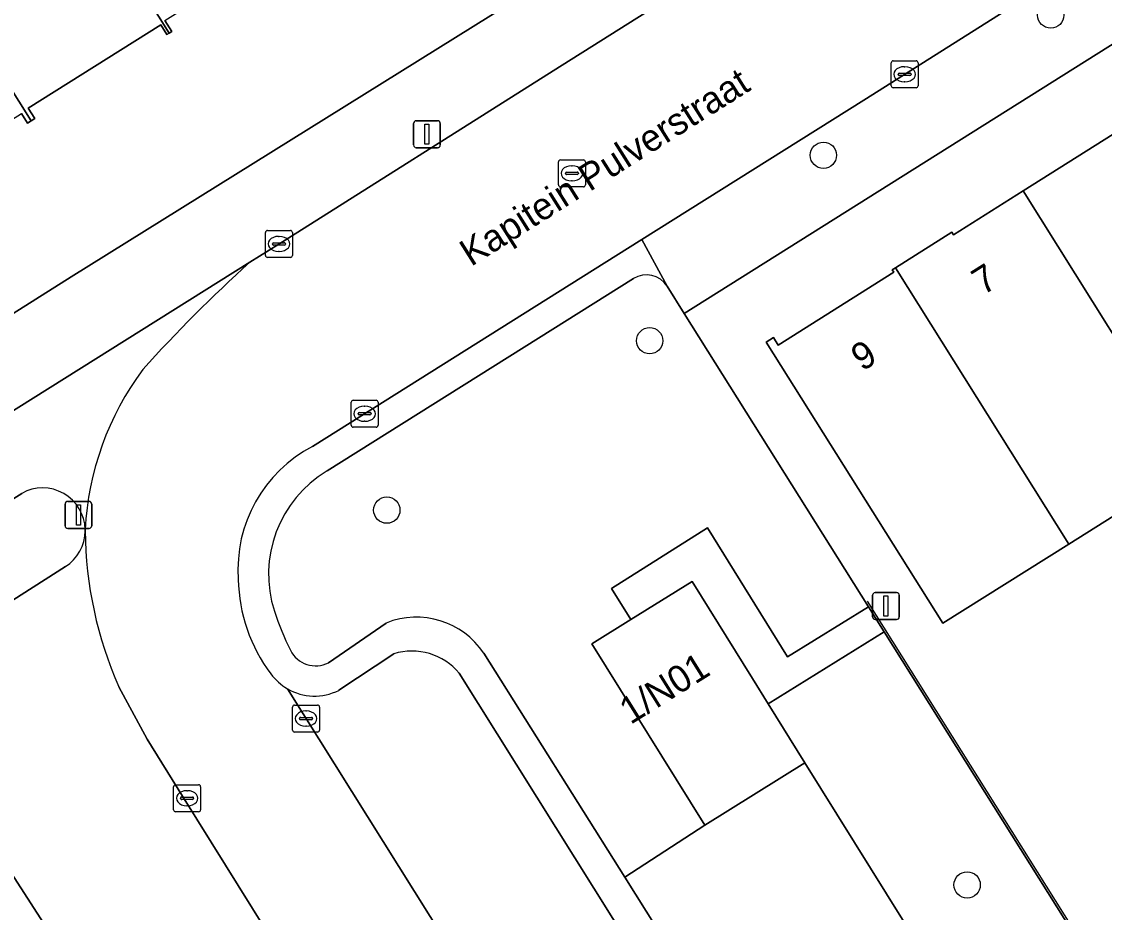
# Model space of a CAD drawing. Extents: x 160077 to 160948, y 386481 to 387498.
# Drawn here: x 160384.29 to 160424.49, y 386952.63 to 386985.67 of the extents above; entities that cross this region are included whole.
import ezdxf

# ---------------------------------------------------------------- set-up
doc = ezdxf.new("R2010")
doc.units = 0
for name, color, linetype in [('IMGEO_Boom', 7, 'Continuous'), ('IMGEO_Erf', 7, 'Continuous'), ('IMGEO_Fietspad_open', 7, 'Continuous'), ('IMGEO_Groenvoorziening', 7, 'Continuous'), ('IMGEO_Hek', 7, 'Continuous'), ('IMGEO_Kolk', 7, 'Continuous'), ('IMGEO_Lichtmast', 7, 'Continuous'), ('IMGEO_Openbare_ruimte_label', 7, 'Continuous'), ('IMGEO_Pand', 7, 'Continuous'), ('IMGEO_Pand_nummerreeks', 7, 'Continuous'), ('IMGEO_Parkeervlak_open', 7, 'Continuous'), ('IMGEO_Rijbaan_lokaal_open', 7, 'Continuous'), ('IMGEO_Rioolput', 7, 'Continuous'), ('IMGEO_Voetpad_open', 7, 'Continuous')]:
    doc.layers.add(name, color=color, linetype=linetype)

msp = doc.modelspace()

# ---------------------------------------------------------------- linework, layer by layer
at = {"layer": 'IMGEO_Boom'}
for centre in [(160422.495, 386985.915), (160414.056, 386980.712), (160407.607, 386973.835), (160397.849, 386967.551), (160419.392, 386953.648)]:
    msp.add_circle(centre, 0.489, dxfattribs=at)
at = {"layer": 'IMGEO_Erf'}
for points in [[(160473.137, 386972.655), (160453.975, 387003.205), (160430.516, 386988.451), (160431.817, 386986.382), (160437.856, 386976.782), (160436.662, 386976.031), (160430.668, 386985.657), (160429.375, 386987.733), (160408.886, 386974.847), (160415.725, 386963.966), (160416.309, 386963.036), (160430.464, 386940.512), (160434.156, 386934.637), (160441.379, 386922.838), (160445.701, 386916.313), (160449.013, 386911.065), (160450.499, 386908.528)], [(160361.943, 386960.929), (160386.133, 386976.2), (160423.489, 386999.46)], [(160389.614, 386985.706), (160389.868, 386985.302), (160389.776, 386985.245), (160389.684, 386985.187), (160389.457, 386985.548), (160384.539, 386982.455), (160384.78, 386982.073), (160384.648, 386981.99), (160384.513, 386981.905), (160384.292, 386982.257)]]:
    msp.add_lwpolyline(points, dxfattribs=at)
msp.add_lwpolyline([(160437.207, 386975.107), (160432.526, 386972.169), (160427.846, 386969.231), (160423.165, 386966.292), (160418.484, 386963.354), (160411.929, 386973.778), (160412.201, 386973.949), (160412.378, 386973.667), (160416.671, 386976.375), (160416.614, 386976.465), (160416.732, 386976.539), (160418.828, 386977.855), (160418.883, 386977.766), (160421.467, 386979.392), (160426.144, 386982.336), (160430.553, 386985.11), (160430.383, 386985.382), (160430.656, 386985.554)], close=True, dxfattribs=at)
at = {"layer": 'IMGEO_Fietspad_open'}
for points in [[(160392.767, 386976.747), (160358.891, 386955.508), (160347.47, 386948.297), (160344.021, 386946.162), (160342.931, 386945.487)], [(160371.041, 386959.892), (160375.091, 386962.445), (160384.296, 386968.171)]]:
    msp.add_lwpolyline(points, dxfattribs=at)
for centre, radius, start, end in [((160429.937, 386935.635), 55.424, 132.1175, 137.9401), ((160397.547, 386966.26), 10.91, 143.4032, 177.0031), ((160385.072, 386966.795), 1.58, 1.2748, 119.4294)]:
    msp.add_arc(centre, radius, start, end, dxfattribs=at)
at = {"layer": 'IMGEO_Groenvoorziening'}
for points in [[(160453.975, 387003.205), (160452.3, 387005.897), (160451.615, 387005.476), (160449.965, 387004.462), (160449.803, 387004.359), (160442.967, 387000.002), (160435.029, 386995.058), (160415.556, 386982.761), (160407.317, 386977.588), (160408.253, 386975.855), (160408.886, 386974.847), (160429.375, 386987.733), (160430.516, 386988.451)], [(160416.309, 386963.036), (160412.008, 386960.369), (160413.372, 386958.18), (160426.082, 386937.782), (160429.547, 386939.941), (160430.464, 386940.512)], [(160413.372, 386958.18), (160409.654, 386955.863), (160406.679, 386953.933), (160423.283, 386927.515), (160428.214, 386930.912), (160426.619, 386933.446), (160424.504, 386936.799), (160426.082, 386937.782)]]:
    msp.add_lwpolyline(points, close=True, dxfattribs=at)
for points in [[(160407.006, 386976.14), (160403.479, 386973.927), (160395.629, 386969.002)], [(160409.756, 386966.888), (160412.722, 386962.104), (160415.725, 386963.966), (160408.886, 386974.847), (160408.253, 386975.855)], [(160401.452, 386962.248), (160406.679, 386953.933), (160409.654, 386955.863), (160405.461, 386962.589), (160406.91, 386963.492), (160406.187, 386964.645), (160409.756, 386966.888)], [(160395.68, 386961.887), (160397.825, 386963.363)]]:
    msp.add_lwpolyline(points, dxfattribs=at)
for centre, radius, start, end in [((160407.486, 386975.371), 0.907, 32.2578, 121.9947), ((160397.921, 386965.172), 4.463, 120.8967, 197.9502), ((160403.403, 386966.983), 10.237, 198.1333, 206.9095), ((160398.945, 386960.549), 3.029, 34.1263, 111.6971), ((160395.209, 386962.82), 1.045, 206.7099, 296.8121)]:
    msp.add_arc(centre, radius, start, end, dxfattribs=at)
at = {"layer": 'IMGEO_Hek'}
msp.add_lwpolyline([(160447.699, 386913.245), (160415.689, 386964.174)], dxfattribs=at)
at = {"layer": 'IMGEO_Kolk'}
for p, q in [((160416.571, 386983.291), (160416.571, 386984.143)), ((160416.646, 386984.217), (160417.498, 386984.217)), ((160417.059, 386983.997), (160417.084, 386983.997)), ((160417.572, 386984.143), (160417.572, 386983.291)), ((160416.83, 386983.711), (160416.83, 386983.723)), ((160417.268, 386983.674), (160416.87, 386983.674)), ((160416.873, 386983.76), (160417.271, 386983.76)), ((160417.314, 386983.723), (160417.314, 386983.711)), ((160417.498, 386983.217), (160416.646, 386983.217)), ((160417.082, 386983.437), (160417.057, 386983.437)), ((160393.345, 386976.998), (160393.345, 386977.85)), ((160393.42, 386977.924), (160394.272, 386977.924)), ((160394.346, 386977.85), (160394.346, 386976.998)), ((160393.647, 386977.467), (160394.045, 386977.467)), ((160393.833, 386977.704), (160393.858, 386977.704)), ((160393.604, 386977.418), (160393.604, 386977.43)), ((160394.042, 386977.381), (160393.644, 386977.381)), ((160393.856, 386977.144), (160393.831, 386977.144)), ((160394.088, 386977.43), (160394.088, 386977.418)), ((160394.272, 386976.924), (160393.42, 386976.924)), ((160396.526, 386970.699), (160396.526, 386971.551)), ((160396.601, 386971.625), (160397.453, 386971.625)), ((160397.527, 386971.551), (160397.527, 386970.699)), ((160396.785, 386971.119), (160396.785, 386971.131)), ((160397.223, 386971.082), (160396.825, 386971.082)), ((160396.828, 386971.168), (160397.226, 386971.168)), ((160397.014, 386971.405), (160397.039, 386971.405)), ((160397.269, 386971.131), (160397.269, 386971.119)), ((160397.453, 386970.625), (160396.601, 386970.625)), ((160397.037, 386970.845), (160397.012, 386970.845)), ((160394.351, 386959.394), (160394.351, 386960.246)), ((160394.426, 386960.32), (160395.278, 386960.32)), ((160395.352, 386960.246), (160395.352, 386959.394)), ((160394.61, 386959.814), (160394.61, 386959.826)), ((160395.048, 386959.777), (160394.65, 386959.777)), ((160394.653, 386959.863), (160395.051, 386959.863)), ((160394.839, 386960.1), (160394.864, 386960.1)), ((160395.094, 386959.826), (160395.094, 386959.814)), ((160394.862, 386959.54), (160394.837, 386959.54)), ((160395.278, 386959.32), (160394.426, 386959.32)), ((160390.011, 386957.364), (160390.863, 386957.364)), ((160389.936, 386956.438), (160389.936, 386957.29)), ((160390.424, 386957.144), (160390.449, 386957.144)), ((160390.937, 386957.29), (160390.937, 386956.438)), ((160390.195, 386956.858), (160390.195, 386956.87)), ((160390.633, 386956.821), (160390.235, 386956.821)), ((160390.238, 386956.907), (160390.636, 386956.907)), ((160390.447, 386956.584), (160390.422, 386956.584)), ((160390.679, 386956.87), (160390.679, 386956.858)), ((160390.863, 386956.364), (160390.011, 386956.364))]:
    msp.add_line(p, q, dxfattribs=at)
for points in [[(160416.571, 386983.291), (160416.571, 386984.143)], [(160416.646, 386984.217), (160417.498, 386984.217)], [(160417.572, 386984.143), (160417.572, 386983.291)], [(160417.498, 386983.217), (160416.646, 386983.217)], [(160393.345, 386976.998), (160393.345, 386977.85)], [(160393.42, 386977.924), (160394.272, 386977.924)], [(160394.346, 386977.85), (160394.346, 386976.998)], [(160394.272, 386976.924), (160393.42, 386976.924)], [(160396.526, 386970.699), (160396.526, 386971.551)], [(160396.601, 386971.625), (160397.453, 386971.625)], [(160397.527, 386971.551), (160397.527, 386970.699)], [(160397.453, 386970.625), (160396.601, 386970.625)], [(160394.351, 386959.394), (160394.351, 386960.246)], [(160394.426, 386960.32), (160395.278, 386960.32)], [(160395.352, 386960.246), (160395.352, 386959.394)], [(160395.278, 386959.32), (160394.426, 386959.32)], [(160390.011, 386957.364), (160390.863, 386957.364)], [(160389.936, 386956.438), (160389.936, 386957.29)], [(160390.937, 386957.29), (160390.937, 386956.438)], [(160390.863, 386956.364), (160390.011, 386956.364)]]:
    msp.add_lwpolyline(points, dxfattribs=at)
for centre, radius, start, end in [((160416.648, 386984.141), 0.0765, 91.552, 178.448), ((160416.648, 386984.141), 0.0765, 91.552, 178.448), ((160417.496, 386984.141), 0.0765, 1.552, 88.448), ((160417.496, 386984.141), 0.0765, 1.552, 88.448), ((160416.87, 386983.72), 0.0403, 85.8775, 175.7526), ((160416.867, 386983.71), 0.0366, 178.938, 274.7102), ((160417.271, 386983.717), 0.043, 264.8664, 352.4533), ((160417.275, 386983.722), 0.0386, 1.7309, 96.639), ((160416.648, 386983.293), 0.0765, 181.552, 268.448), ((160416.648, 386983.293), 0.0765, 181.552, 268.448), ((160417.496, 386983.293), 0.0765, 271.552, 358.448), ((160417.496, 386983.293), 0.0765, 271.552, 358.448), ((160393.422, 386977.848), 0.0765, 91.552, 178.448), ((160393.422, 386977.848), 0.0765, 91.552, 178.448), ((160394.27, 386977.848), 0.0765, 1.552, 88.448), ((160394.27, 386977.848), 0.0765, 1.552, 88.448), ((160393.644, 386977.427), 0.0403, 85.8775, 175.7526), ((160394.049, 386977.429), 0.0386, 1.7309, 96.639), ((160393.641, 386977.417), 0.0366, 178.938, 274.7102), ((160394.045, 386977.424), 0.043, 264.8664, 352.4533), ((160393.422, 386977), 0.0765, 181.552, 268.448), ((160393.422, 386977), 0.0765, 181.552, 268.448), ((160394.27, 386977), 0.0765, 271.552, 358.448), ((160394.27, 386977), 0.0765, 271.552, 358.448), ((160396.603, 386971.549), 0.0765, 91.552, 178.448), ((160396.603, 386971.549), 0.0765, 91.552, 178.448), ((160397.451, 386971.549), 0.0765, 1.552, 88.448), ((160397.451, 386971.549), 0.0765, 1.552, 88.448), ((160396.825, 386971.128), 0.0403, 85.8775, 175.7526), ((160396.822, 386971.118), 0.0366, 178.938, 274.7102), ((160397.226, 386971.125), 0.043, 264.8664, 352.4533), ((160397.23, 386971.13), 0.0386, 1.7309, 96.639), ((160396.603, 386970.701), 0.0765, 181.552, 268.448), ((160396.603, 386970.701), 0.0765, 181.552, 268.448), ((160397.451, 386970.701), 0.0765, 271.552, 358.448), ((160397.451, 386970.701), 0.0765, 271.552, 358.448), ((160394.428, 386960.244), 0.0765, 91.552, 178.448), ((160394.428, 386960.244), 0.0765, 91.552, 178.448), ((160395.276, 386960.244), 0.0765, 1.552, 88.448), ((160395.276, 386960.244), 0.0765, 1.552, 88.448), ((160394.65, 386959.823), 0.0403, 85.8775, 175.7526), ((160394.647, 386959.813), 0.0366, 178.938, 274.7102), ((160395.051, 386959.82), 0.043, 264.8664, 352.4533), ((160395.055, 386959.825), 0.0386, 1.7309, 96.639), ((160394.428, 386959.396), 0.0765, 181.552, 268.448), ((160394.428, 386959.396), 0.0765, 181.552, 268.448), ((160395.276, 386959.396), 0.0765, 271.552, 358.448), ((160395.276, 386959.396), 0.0765, 271.552, 358.448), ((160390.013, 386957.288), 0.0765, 91.552, 178.448), ((160390.013, 386957.288), 0.0765, 91.552, 178.448), ((160390.861, 386957.288), 0.0765, 1.552, 88.448), ((160390.861, 386957.288), 0.0765, 1.552, 88.448), ((160390.235, 386956.867), 0.0403, 85.8775, 175.7526), ((160390.232, 386956.857), 0.0366, 178.938, 274.7102), ((160390.636, 386956.864), 0.043, 264.8664, 352.4533), ((160390.64, 386956.869), 0.0386, 1.7309, 96.639), ((160390.013, 386956.44), 0.0765, 181.552, 268.448), ((160390.013, 386956.44), 0.0765, 181.552, 268.448), ((160390.861, 386956.44), 0.0765, 271.552, 358.448), ((160390.861, 386956.44), 0.0765, 271.552, 358.448)]:
    msp.add_arc(centre, radius, start, end, dxfattribs=at)
for centre, major_axis, ratio, start_param, end_param in [((160417.058, 386983.717), (-0.387, 0.002), 0.722429, 4.712389, 7.853982), ((160417.083, 386983.717), (-0.39, 0.002), 0.717154, 1.570796, 4.712389), ((160393.832, 386977.424), (-0.387, 0.002), 0.722429, 4.712389, 7.853982), ((160393.857, 386977.424), (-0.39, 0.002), 0.717154, 1.570796, 4.712389), ((160397.013, 386971.125), (-0.387, 0.002), 0.722429, 4.712389, 7.853982), ((160397.038, 386971.125), (-0.39, 0.002), 0.717154, 1.570796, 4.712389), ((160394.838, 386959.82), (-0.387, 0.002), 0.722429, 4.712389, 7.853982), ((160394.863, 386959.82), (-0.39, 0.002), 0.717154, 1.570796, 4.712389), ((160390.423, 386956.864), (-0.387, 0.002), 0.722429, 4.712389, 7.853982), ((160390.448, 386956.864), (-0.39, 0.002), 0.717154, 1.570796, 4.712389)]:
    msp.add_ellipse(centre, major_axis=major_axis, ratio=ratio, start_param=start_param, end_param=end_param, dxfattribs=at)
at = {"layer": 'IMGEO_Lichtmast'}
for p, q in [((160398.843, 386981.094), (160398.843, 386981.894)), ((160398.843, 386981.894), (160398.843, 386981.094)), ((160398.943, 386981.994), (160399.733, 386981.994)), ((160399.733, 386981.994), (160398.943, 386981.994)), ((160399.833, 386981.894), (160399.833, 386981.094)), ((160399.833, 386981.094), (160399.833, 386981.894)), ((160399.733, 386980.994), (160398.943, 386980.994)), ((160398.943, 386980.994), (160399.733, 386980.994)), ((160386.005, 386967.873), (160386.795, 386967.873)), ((160386.795, 386967.873), (160386.005, 386967.873)), ((160385.905, 386966.973), (160385.905, 386967.773)), ((160385.905, 386967.773), (160385.905, 386966.973)), ((160386.895, 386967.773), (160386.895, 386966.973)), ((160386.895, 386966.973), (160386.895, 386967.773)), ((160386.795, 386966.873), (160386.005, 386966.873)), ((160386.005, 386966.873), (160386.795, 386966.873)), ((160415.882, 386963.592), (160415.882, 386964.392)), ((160415.882, 386964.392), (160415.882, 386963.592)), ((160415.982, 386964.492), (160416.772, 386964.492)), ((160416.772, 386964.492), (160415.982, 386964.492)), ((160416.872, 386964.392), (160416.872, 386963.592)), ((160416.872, 386963.592), (160416.872, 386964.392)), ((160416.772, 386963.492), (160415.982, 386963.492)), ((160415.982, 386963.492), (160416.772, 386963.492))]:
    msp.add_line(p, q, dxfattribs=at)
for points in [[(160399.263, 386981.869), (160399.413, 386981.869), (160399.413, 386981.119), (160399.263, 386981.119), (160399.263, 386981.869)], [(160386.325, 386967.748), (160386.475, 386967.748), (160386.475, 386966.998), (160386.325, 386966.998), (160386.325, 386967.748)], [(160416.302, 386964.367), (160416.452, 386964.367), (160416.452, 386963.617), (160416.302, 386963.617), (160416.302, 386964.367)]]:
    msp.add_lwpolyline(points, dxfattribs=at)
for centre, start, end in [((160398.943, 386981.894), 90, 180), ((160398.943, 386981.894), 90, 180), ((160399.733, 386981.894), 0, 90), ((160399.733, 386981.894), 360, 90), ((160398.943, 386981.094), 180, 270), ((160398.943, 386981.094), 180, 270), ((160399.733, 386981.094), 270, 0), ((160399.733, 386981.094), 270, 0), ((160386.005, 386967.773), 90, 180), ((160386.005, 386967.773), 90, 180), ((160386.795, 386967.773), 0, 90), ((160386.795, 386967.773), 360, 90), ((160386.005, 386966.973), 180, 270), ((160386.005, 386966.973), 180, 270), ((160386.795, 386966.973), 270, 0), ((160386.795, 386966.973), 270, 0), ((160415.982, 386964.392), 90, 180), ((160415.982, 386964.392), 90, 180), ((160416.772, 386964.392), 0, 90), ((160416.772, 386964.392), 360, 90), ((160415.982, 386963.592), 180, 270), ((160415.982, 386963.592), 180, 270), ((160416.772, 386963.592), 270, 0), ((160416.772, 386963.592), 270, 0)]:
    msp.add_arc(centre, 0.1, start, end, dxfattribs=at)
at = {"layer": 'IMGEO_Pand'}
for points in [[(160390.709, 386995.08), (160385.602, 386991.891), (160389.776, 386985.245), (160389.868, 386985.302), (160389.614, 386985.706), (160394.508, 386988.784), (160394.735, 386988.423), (160394.846, 386988.493)], [(160384.648, 386981.99), (160384.78, 386982.073), (160384.539, 386982.455), (160389.457, 386985.548), (160389.684, 386985.187), (160389.776, 386985.245), (160385.602, 386991.891), (160380.45, 386988.673)], [(160379.505, 386978.742), (160379.617, 386978.812), (160379.389, 386979.174), (160384.292, 386982.257), (160384.513, 386981.905), (160384.648, 386981.99), (160380.45, 386988.673), (160375.291, 386985.452)], [(160426.144, 386982.336), (160421.467, 386979.392), (160427.846, 386969.231), (160432.526, 386972.169)], [(160421.467, 386979.392), (160418.883, 386977.766), (160418.828, 386977.855), (160416.732, 386976.539), (160423.165, 386966.292), (160427.846, 386969.231)], [(160416.732, 386976.539), (160416.614, 386976.465), (160416.671, 386976.375), (160412.378, 386973.667), (160412.201, 386973.949), (160411.929, 386973.778), (160418.484, 386963.354), (160423.165, 386966.292)], [(160411.427, 386961.301), (160409.179, 386964.907), (160406.91, 386963.492), (160405.461, 386962.589), (160409.654, 386955.863), (160413.372, 386958.18), (160412.008, 386960.369)]]:
    msp.add_lwpolyline(points, close=True, dxfattribs=at)
at = {"layer": 'IMGEO_Parkeervlak_open'}
for points in [[(160385.916, 386965.458), (160379.288, 386961.228), (160386.077, 386950.727), (160387.305, 386948.746), (160389.414, 386950.096)], [(160398.108, 386962.224), (160396.066, 386960.866)], [(160394.157, 386960.926), (160407.72, 386939.3), (160421.339, 386917.461), (160423.535, 386918.746), (160426.233, 386920.508), (160400.541, 386961.501)], [(160390.779, 386948.087), (160388.615, 386946.721), (160388.875, 386946.31), (160390.688, 386943.438), (160411.153, 386911.02), (160416.321, 386914.248), (160416.924, 386914.647), (160402.32, 386937.614), (160390.263, 386956.936), (160388.955, 386959.055), (160387.906, 386960.997)]]:
    msp.add_lwpolyline(points, dxfattribs=at)
for centre, radius, start, end in [((160385.075, 386966.792), 1.577, 302.2191, 359.5319), ((160401.172, 386966.901), 14.521, 180.4821, 203.9915), ((160398.777, 386960.021), 2.302, 39.9942, 106.9057), ((160395.167, 386962.657), 2.004, 239.7466, 296.6529)]:
    msp.add_arc(centre, radius, start, end, dxfattribs=at)
at = {"layer": 'IMGEO_Rijbaan_lokaal_open'}
for points in [[(160435.029, 386995.058), (160442.967, 387000.002), (160449.803, 387004.359), (160449.965, 387004.462), (160451.615, 387005.476), (160448.207, 387011.088), (160447.956, 387011.473), (160446.914, 387010.811), (160443.332, 387008.554), (160429.747, 387000), (160420.855, 386994.441), (160404.019, 386983.85), (160393.843, 386977.421), (160392.767, 386976.747)], [(160395.093, 386969.913), (160407.317, 386977.588), (160415.556, 386982.761), (160435.029, 386995.058)], [(160386.652, 386966.83), (160386.652, 386966.779)], [(160387.906, 386960.997), (160388.955, 386959.055), (160390.263, 386956.936), (160402.32, 386937.614), (160416.924, 386914.647), (160416.321, 386914.248), (160419.644, 386908.926), (160414.476, 386905.699), (160418.626, 386899.176), (160445.701, 386916.313), (160441.379, 386922.838), (160437.094, 386920.111), (160426.867, 386913.603), (160423.535, 386918.746), (160421.339, 386917.461), (160407.72, 386939.3), (160394.157, 386960.926)]]:
    msp.add_lwpolyline(points, dxfattribs=at)
for centre, radius, start, end in [((160429.937, 386935.635), 55.424, 132.1175, 137.9401), ((160397.547, 386966.26), 10.91, 143.4032, 177.0031), ((160397.459, 386965.354), 5.136, 117.4286, 184.141), ((160401.172, 386966.901), 14.521, 180.4821, 203.9915), ((160398.309, 386965.084), 5.974, 180.9722, 217.1576), ((160395.155, 386962.643), 1.986, 215.9898, 239.8386)]:
    msp.add_arc(centre, radius, start, end, dxfattribs=at)
at = {"layer": 'IMGEO_Rioolput'}
for p, q in [((160404.219, 386979.616), (160404.219, 386980.468)), ((160404.294, 386980.542), (160405.146, 386980.542)), ((160404.707, 386980.322), (160404.732, 386980.322)), ((160405.22, 386980.468), (160405.22, 386979.616)), ((160404.478, 386980.036), (160404.478, 386980.048)), ((160404.916, 386979.999), (160404.518, 386979.999)), ((160404.521, 386980.085), (160404.919, 386980.085)), ((160404.962, 386980.048), (160404.962, 386980.036)), ((160405.146, 386979.542), (160404.294, 386979.542)), ((160404.73, 386979.762), (160404.705, 386979.762))]:
    msp.add_line(p, q, dxfattribs=at)
for points in [[(160404.219, 386979.616), (160404.219, 386980.468)], [(160404.294, 386980.542), (160405.146, 386980.542)], [(160405.22, 386980.468), (160405.22, 386979.616)], [(160405.146, 386979.542), (160404.294, 386979.542)]]:
    msp.add_lwpolyline(points, dxfattribs=at)
for centre, radius, start, end in [((160404.296, 386980.466), 0.0765, 91.552, 178.448), ((160404.296, 386980.466), 0.0765, 91.552, 178.448), ((160405.144, 386980.466), 0.0765, 1.552, 88.448), ((160405.144, 386980.466), 0.0765, 1.552, 88.448), ((160404.518, 386980.045), 0.0403, 85.8775, 175.7526), ((160404.515, 386980.035), 0.0366, 178.938, 274.7102), ((160404.919, 386980.042), 0.043, 264.8664, 352.4533), ((160404.923, 386980.047), 0.0386, 1.7309, 96.639), ((160404.296, 386979.618), 0.0765, 181.552, 268.448), ((160404.296, 386979.618), 0.0765, 181.552, 268.448), ((160405.144, 386979.618), 0.0765, 271.552, 358.448), ((160405.144, 386979.618), 0.0765, 271.552, 358.448)]:
    msp.add_arc(centre, radius, start, end, dxfattribs=at)
for centre, major_axis, ratio, start_param, end_param in [((160404.706, 386980.042), (-0.387, 0.002), 0.722429, 4.712389, 7.853982), ((160404.731, 386980.042), (-0.39, 0.002), 0.717154, 1.570796, 4.712389)]:
    msp.add_ellipse(centre, major_axis=major_axis, ratio=ratio, start_param=start_param, end_param=end_param, dxfattribs=at)
at = {"layer": 'IMGEO_Voetpad_open'}
for points in [[(160444.618, 387012.806), (160424.667, 387000.196), (160424.356, 387000), (160423.489, 386999.46), (160386.133, 386976.2), (160361.943, 386960.929), (160357.431, 386958.261), (160357.402, 386958.269), (160353.425, 386955.793), (160346.707, 386951.396), (160342.413, 386948.748), (160344.021, 386946.162), (160347.47, 386948.297), (160358.891, 386955.508), (160392.767, 386976.747), (160393.843, 386977.421), (160404.019, 386983.85), (160420.855, 386994.441)], [(160408.253, 386975.855), (160407.317, 386977.588), (160395.093, 386969.913)], [(160395.629, 386969.002), (160403.479, 386973.927), (160407.006, 386976.14)], [(160384.296, 386968.171), (160375.091, 386962.445), (160380.863, 386953.4), (160380.291, 386953.014), (160381.9, 386950.487), (160382.328, 386950.748), (160383.799, 386948.34), (160385.948, 386945.002), (160388.875, 386946.31), (160388.615, 386946.721), (160390.779, 386948.087)], [(160386.652, 386966.779), (160386.652, 386966.83)], [(160389.414, 386950.096), (160387.305, 386948.746), (160386.077, 386950.727), (160379.288, 386961.228), (160385.916, 386965.458)], [(160397.825, 386963.363), (160395.68, 386961.887)], [(160396.066, 386960.866), (160398.108, 386962.224)], [(160400.541, 386961.501), (160426.233, 386920.508), (160427.264, 386921.181), (160423.283, 386927.515), (160406.679, 386953.933), (160401.452, 386962.248)]]:
    msp.add_lwpolyline(points, dxfattribs=at)
msp.add_lwpolyline([(160416.309, 386963.036), (160415.725, 386963.966), (160412.722, 386962.104), (160409.756, 386966.888), (160406.187, 386964.645), (160406.91, 386963.492), (160409.179, 386964.907), (160411.427, 386961.301), (160412.008, 386960.369)], close=True, dxfattribs=at)
for centre, radius, start, end in [((160407.486, 386975.371), 0.907, 32.2578, 121.9947), ((160397.459, 386965.354), 5.136, 117.4286, 184.141), ((160397.921, 386965.172), 4.463, 120.8967, 197.9502), ((160385.072, 386966.795), 1.58, 1.2748, 119.4294), ((160385.075, 386966.792), 1.577, 302.2191, 359.5319), ((160398.309, 386965.084), 5.974, 180.9722, 217.1576), ((160403.403, 386966.983), 10.237, 198.1333, 206.9095), ((160398.945, 386960.549), 3.029, 34.1263, 111.6971), ((160395.209, 386962.82), 1.045, 206.7099, 296.8121), ((160398.777, 386960.021), 2.302, 39.9942, 106.9057), ((160395.155, 386962.643), 1.986, 215.9898, 239.8386), ((160395.167, 386962.657), 2.004, 239.7466, 296.6529)]:
    msp.add_arc(centre, radius, start, end, dxfattribs=at)

# ---------------------------------------------------------------- texts
at = {"layer": 'IMGEO_Openbare_ruimte_label'}
msp.add_text('Kapitein Pulverstraat', height=1, rotation=32.2604, dxfattribs=at).set_placement((160400.975, 386976.568))
at = {"layer": 'IMGEO_Pand_nummerreeks'}
for s, rotation, p in [('7', 32.183, (160419.98, 386975.503)), ('9', 32.2461, (160415.497, 386972.678)), ('1/N01', 32.0054, (160406.896, 386959.578))]:
    msp.add_text(s, height=1, rotation=rotation, dxfattribs=at).set_placement(p)

doc.saveas('drawing.dxf')
